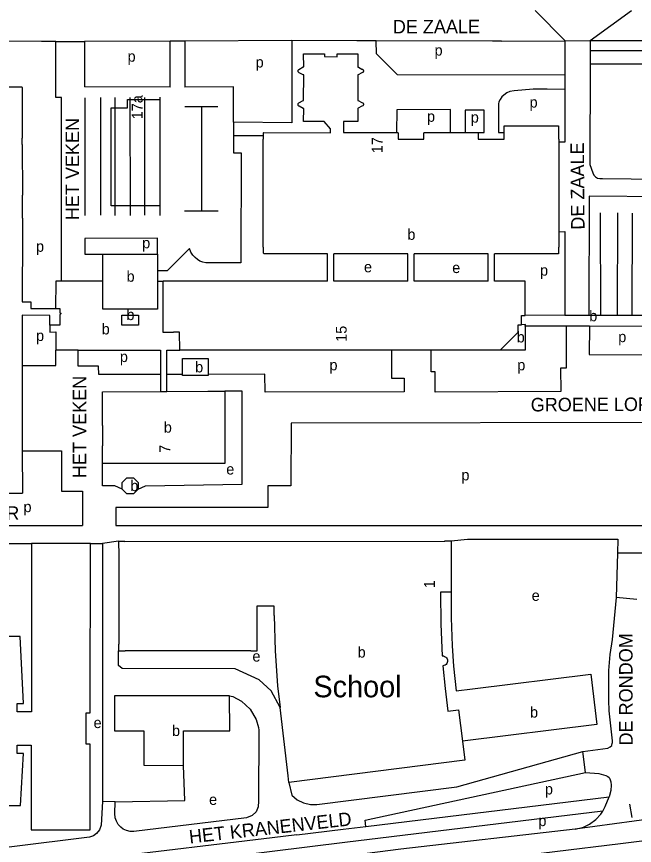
# Model space of a CAD drawing. Extents: x 161494 to 163033, y 383688 to 384862.
# Drawn here: x 162005.1 to 162234.2, y 384072.6 to 384379.7 of the extents above; entities that cross this region are included whole.
import ezdxf

# ---------------------------------------------------------------- set-up
doc = ezdxf.new("R2010")
doc.units = 0
for name, color, linetype in [('BLT_Basislijn', 7, 'Continuous'), ('BLT_Bebouwing', 7, 'Continuous'), ('BLT_Bebouwing_beschrifting', 7, 'Continuous'), ('BLT_Centroide', 7, 'Continuous'), ('BLT_Huisnummer', 7, 'Continuous'), ('BLT_Huisnummer_zonder_bebouwing', 7, 'Continuous'), ('BLT_Onderdoorgang_en_onderverdeling', 7, 'Continuous'), ('BLT_Onderverdeling_panden', 7, 'Continuous'), ('BLT_Plantopo', 7, 'Continuous'), ('BLT_Straatnaam', 7, 'Continuous'), ('BLT_Vlakafsluiter', 7, 'Continuous')]:
    doc.layers.add(name, color=color, linetype=linetype)

msp = doc.modelspace()

# ---------------------------------------------------------------- linework, layer by layer
at = {"layer": 'BLT_Basislijn'}
for p, q in [((162019.69, 384370.44), (162014.35, 384370.42)), ((162019.69, 384370.44), (162030.32, 384370.48)), ((162030.32, 384370.48), (162030.31, 384353.66)), ((162062.08, 384370.61), (162030.32, 384370.48)), ((162062.07, 384353.6), (162062.08, 384370.61)), ((162067.51, 384370.63), (162062.08, 384370.61)), ((162107.23, 384370.78), (162067.51, 384370.63)), ((162067.51, 384370.63), (162067.58, 384353.53)), ((162138.48, 384370.7), (162131.74, 384370.71)), ((162184.93, 384370.63), (162208.56, 384370.74)), ((162208.56, 384370.74), (162217.82, 384370.78)), ((162217.82, 384370.78), (162249.53, 384370.93)), ((162249.53, 384367.05), (162217.81, 384367.06)), ((162249.53, 384362.05), (162217.8, 384362.06)), ((162062.07, 384353.6), (162030.31, 384353.66)), ((162030.4, 384349.64), (162030.4, 384306.02)), ((162036.21, 384349.74), (162036.21, 384306.05)), ((162041.71, 384305.96), (162041.67, 384349.71)), ((162047.2, 384349.73), (162047.22, 384306)), ((162052.72, 384306.09), (162052.71, 384349.76)), ((162058.35, 384305.96), (162058.38, 384349.81)), ((162067.53, 384346.36), (162079.8, 384346.36)), ((162073.66, 384346.36), (162073.68, 384307.72)), ((162085.59, 384340.57), (162085.6, 384335.57)), ((162085.6, 384335.57), (162096.65, 384335.59)), ((162067.4, 384307.75), (162079.85, 384307.68)), ((162221.59, 384306.94), (162221.63, 384268.94)), ((162227.91, 384306.92), (162227.79, 384268.92)), ((162233.39, 384306.88), (162233.27, 384268.9)), ((162044.3, 384204.56), (162041.59, 384205.78)), ((161965.96, 384191.05), (162029.59, 384191.05)), ((161990.93, 384184.45), (162010.71, 384184.45)), ((162247.24, 384180.87), (162227.98, 384180.87)), ((162232.42, 384087.78), (162233.3, 384082.95)), ((162222.59, 384085.25), (162126.86, 384073.58)), ((162099.94, 384075.38), (162038.28, 384067.96)), ((162109.12, 384076.49), (162099.94, 384075.38)), ((162126.86, 384073.58), (162015.41, 384059.99))]:
    msp.add_line(p, q, dxfattribs=at)
for points in [[(162014.35, 384370.42), (161952.43, 384370.98)], [(162021.76, 384281.63), (162021.76, 384349.7), (162019.67, 384349.7), (162019.69, 384370.44)], [(162107.23, 384370.78), (162107.16, 384340.38), (162085.59, 384340.57)], [(162131.74, 384370.71), (162131.34, 384370.71), (162107.23, 384370.78)], [(162184.93, 384370.63), (162181.64, 384370.54), (162138.48, 384370.7)], [(162208.55, 384357.94), (162146.36, 384358.05), (162138.57, 384365.87), (162138.48, 384370.7)], [(162208.55, 384357.94), (162208.56, 384370.74)], [(162217.82, 384370.78), (162217.81, 384367.06)], [(162217.81, 384367.06), (162217.8, 384362.06)], [(162217.8, 384362.06), (162217.74, 384324.93), (162218.77, 384321.83), (162219.2, 384320.92), (162219.82, 384320.28), (162220.55, 384319.86), (162221.38, 384319.65), (162222.38, 384319.64), (162243.64, 384319.46), (162245.34, 384318.42), (162249.4, 384318.43), (162249.42, 384323.47)], [(162208.55, 384352.69), (162208.55, 384357.94)], [(162085.59, 384340.57), (162085.56, 384353.63), (162067.58, 384353.53)], [(162208.55, 384352.69), (162201.85, 384352.82), (162196.72, 384352.85), (162189.59, 384352.24), (162188.09, 384351.94), (162186.9, 384351.42), (162185.79, 384350.61), (162185.11, 384349.93), (162184.45, 384348.98), (162184, 384348.08), (162183.86, 384347.39), (162183.81, 384345.03), (162183.82, 384336.72), (162185.97, 384336.71)], [(162206.27, 384333.28), (162208.53, 384333.29), (162208.55, 384352.69)], [(162166.08, 384336.76), (162166.06, 384345.25), (162146.1, 384345.19), (162146.08, 384336.77)], [(162176.15, 384336.75), (162178.48, 384336.74), (162178.47, 384345.02), (162171.44, 384345.02), (162171.43, 384336.76)], [(162085.6, 384335.57), (162085.59, 384329.24), (162088.41, 384329.24), (162088.36, 384288.41), (162076.5, 384288.41), (162075.36, 384288.47), (162074.18, 384288.72), (162073.14, 384289.12), (162072.27, 384289.62), (162071.31, 384290.37), (162070.48, 384291.29), (162069.77, 384292.41), (162069.26, 384293.73), (162061.02, 384285.49), (162057.45, 384285.5)], [(162245.59, 384286.75), (162245.56, 384312.93), (162217.49, 384313.17), (162217.33, 384268.95)], [(162206.25, 384299.94), (162208.48, 384300.02), (162208.38, 384268.98)], [(162057.39, 384291.62), (162057.39, 384297.64), (162030.4, 384297.42), (162030.4, 384291.63), (162037.08, 384291.63)], [(162208.96, 384264.97), (162208.91, 384249.42), (162206.88, 384249.43), (162206.92, 384240.72), (162160.39, 384240.54), (162160.4, 384248.07), (162158.82, 384248.07), (162158.84, 384256.09)], [(162217.54, 384264.95), (162217.51, 384254.43), (162240.28, 384254.3), (162240.29, 384264.88)], [(162007.27, 384250.4), (162019.71, 384250.4), (162019.71, 384256.08)], [(162058.48, 384247.11), (162035.63, 384247.1), (162035.57, 384250.09), (162027.96, 384250.11), (162027.94, 384256.08)], [(162144.12, 384256.1), (162144.12, 384245.68), (162148.9, 384245.69), (162148.88, 384240.66), (162097.29, 384240.52), (162097.24, 384247.13), (162076.15, 384247.12)], [(162066.61, 384247.11), (162060.85, 384247.11)], [(162050.27, 384204.53), (162052.97, 384205.77), (162088.77, 384206.48), (162088.81, 384240.89), (162082.42, 384240.9)], [(162247.21, 384191.05), (162247.31, 384229.25), (162106.92, 384229), (162106.81, 384205.82), (162098.37, 384205.81), (162098.37, 384197.75), (162041.94, 384197.72), (162041.92, 384191.05), (162247.21, 384191.05)], [(162007.28, 384218.83), (162021.75, 384218.83), (162021.75, 384203.81), (162029.62, 384203.8), (162029.59, 384191.05)], [(162041.59, 384205.78), (162037, 384205.76), (162036.97, 384214.11)], [(162166.31, 384185.38), (162172.4, 384186.05), (162228.13, 384186.05)], [(162228.13, 384186.05), (162227.98, 384180.87)], [(162032.55, 384184.43), (162037.02, 384184.43)], [(162037.02, 384184.43), (162037.04, 384088.82)], [(162227.98, 384180.87), (162227.52, 384164.46)], [(162227.52, 384164.46), (162226.02, 384148.8)], [(162226.02, 384148.8), (162225.15, 384143.31), (162224.67, 384137.43), (162224.57, 384126.39), (162224.74, 384122.4), (162225.26, 384117.92)], [(162102.89, 384123.64), (162099.51, 384129.85), (162095.13, 384133.9), (162086.14, 384137.97), (162044.34, 384138.09), (162042.99, 384139.27), (162042.97, 384144.67)], [(162084.15, 384127.98), (162085.35, 384127.68), (162088.53, 384126.04), (162091.72, 384123), (162093.98, 384119.23), (162094.84, 384116.31), (162094.96, 384115.27), (162094.86, 384088.92), (162094.74, 384086.81), (162093.96, 384085.04), (162092.56, 384083.64), (162090.45, 384082.79), (162048.68, 384077.67), (162047.3, 384077.68), (162045.86, 384078.03), (162044.73, 384078.57), (162043.77, 384079.28), (162042.84, 384080.31), (162042.15, 384081.53), (162041.75, 384082.79), (162041.62, 384084.43), (162041.68, 384088.69)], [(162225.26, 384117.92), (162226.02, 384111.31), (162226.02, 384110.45)], [(162215.09, 384107.35), (162224.34, 384108.57), (162225.26, 384109.03), (162225.82, 384109.61), (162226.02, 384110.45)], [(162106.09, 384095.92), (162107.27, 384091.16), (162109.14, 384089.5), (162111.49, 384088.28), (162114.17, 384087.69), (162116.52, 384087.75), (162168.4, 384094.24), (162215.09, 384107.35)], [(162041.68, 384088.69), (162067.5, 384089.14), (162067.07, 384102.21)], [(162134.69, 384079.58), (162134.41, 384081.91), (162216.12, 384099.58)], [(162216.12, 384099.58), (162221.09, 384099.24), (162223.58, 384098.49), (162224.36, 384098.12), (162224.84, 384097.7), (162225.1, 384097.23), (162225.48, 384096.06), (162225.64, 384094.84), (162225.46, 384092.91), (162224.84, 384090.56)], [(162134.69, 384079.58), (162224.84, 384090.56)], [(162222.59, 384085.25), (162223.45, 384086.96), (162224.84, 384090.56)], [(162037.04, 384088.82), (162036.53, 384080.07), (162035.9, 384078.31), (162034.83, 384076.99), (162033.62, 384076.14), (162032.14, 384075.62), (161973.45, 384068.36), (161971.82, 384068.3), (161970.32, 384068.57), (161968.94, 384069.14), (161967.71, 384069.97), (161966.53, 384071.23), (161965.71, 384072.68), (161965.29, 384073.99), (161965.13, 384075.37), (161965.09, 384077.77), (161965.12, 384080.52)], [(162041.68, 384088.69), (162037.04, 384088.82)], [(162212.3, 384078.63), (162215.37, 384079.36), (162217.58, 384080.42), (162219.99, 384082.13), (162221.75, 384084.12), (162222.59, 384085.25)], [(162212.3, 384078.63), (162147.57, 384071.14), (162099.53, 384065.02), (162042.92, 384058.28)], [(162109.12, 384076.49), (162126.25, 384078.55), (162134.69, 384079.58)], [(162257.94, 384076.77), (162229.07, 384073.11), (162180.34, 384067.19), (162170.91, 384066.06)]]:
    msp.add_lwpolyline(points, dxfattribs=at)
at = {"layer": 'BLT_Bebouwing'}
for p, q in [((162007.37, 384304.96), (162007.37, 384313.57)), ((162120.44, 384281.64), (162120.44, 384291.78)), ((162122.84, 384281.64), (162122.81, 384291.78)), ((162150.21, 384281.65), (162150.18, 384291.78)), ((162152.58, 384281.65), (162152.58, 384291.78)), ((162179.98, 384281.65), (162179.97, 384291.78)), ((162182.33, 384281.65), (162182.36, 384291.78)), ((162057.45, 384281.64), (162059.53, 384281.65)), ((162208.38, 384268.98), (162193.79, 384269.02)), ((162217.33, 384268.95), (162208.38, 384268.98)), ((162221.63, 384268.94), (162217.33, 384268.95)), ((162227.79, 384268.92), (162221.63, 384268.94)), ((162233.27, 384268.9), (162227.79, 384268.92)), ((162238.76, 384268.88), (162233.27, 384268.9)), ((162208.96, 384264.97), (162193.79, 384265.02)), ((162217.54, 384264.95), (162208.96, 384264.97)), ((162240.29, 384264.88), (162217.54, 384264.95)), ((162027.94, 384256.08), (162019.71, 384256.08)), ((162076.15, 384252.99), (162076.15, 384247.12)), ((162076.15, 384247.12), (162076.15, 384246.67)), ((162007.27, 384234.35), (162007.28, 384218.83)), ((162166.31, 384185.38), (162166.3, 384166.4)), ((162084.15, 384127.98), (162041.43, 384127.99)), ((162105.91, 384098.32), (162102.89, 384123.64)), ((162220.29, 384117.37), (162170.48, 384111.23))]:
    msp.add_line(p, q, dxfattribs=at)
for points in [[(162111.61, 384361.02), (162111.59, 384365.87), (162119.27, 384365.88), (162119.28, 384364.88), (162124, 384364.84), (162124, 384365.86), (162131.7, 384365.86), (162131.68, 384361)], [(162111.6, 384358.05), (162111.43, 384358.05), (162109.98, 384358.89), (162109.82, 384358.97), (162109.71, 384359.07), (162109.63, 384359.18), (162109.58, 384359.28), (162109.55, 384359.36), (162109.53, 384359.46), (162109.52, 384359.58), (162109.55, 384359.76), (162109.61, 384359.88), (162109.67, 384359.98), (162109.82, 384360.12), (162111.41, 384361.02), (162111.61, 384361.02)], [(162131.68, 384361), (162131.87, 384361), (162133.19, 384360.27), (162133.43, 384360.16), (162133.53, 384360.09), (162133.62, 384359.98), (162133.71, 384359.83), (162133.75, 384359.68), (162133.76, 384359.55), (162133.76, 384359.46), (162133.75, 384359.36), (162133.7, 384359.23), (162133.63, 384359.1), (162133.56, 384359.02), (162133.45, 384358.93), (162133.21, 384358.82), (162131.86, 384358.08), (162131.67, 384358.08)], [(162111.59, 384348.6), (162111.6, 384358.05)], [(162131.67, 384358.08), (162131.68, 384348.64)], [(161975.98, 384353.62), (162000, 384353.62), (162007.04, 384353.64), (162007.04, 384353.41), (162007.27, 384353.41), (162007.26, 384334.69)], [(162111.6, 384345.67), (162111.42, 384345.67), (162109.92, 384346.5), (162109.81, 384346.55), (162109.72, 384346.62), (162109.64, 384346.71), (162109.58, 384346.8), (162109.52, 384346.95), (162109.5, 384347.09), (162109.5, 384347.23), (162109.54, 384347.37), (162109.6, 384347.48), (162109.66, 384347.57), (162109.74, 384347.65), (162109.85, 384347.72), (162111.39, 384348.6), (162111.59, 384348.6)], [(162131.68, 384348.64), (162131.84, 384348.65), (162133.22, 384347.9), (162133.52, 384347.73), (162133.59, 384347.66), (162133.67, 384347.56), (162133.72, 384347.46), (162133.76, 384347.32), (162133.77, 384347.17), (162133.76, 384347.07), (162133.74, 384346.94), (162133.69, 384346.83), (162133.63, 384346.73), (162133.56, 384346.66), (162133.49, 384346.59), (162133.21, 384346.46), (162131.85, 384345.7), (162131.69, 384345.69)], [(162096.65, 384335.59), (162096.65, 384336.56), (162096.86, 384336.77), (162121.5, 384336.6), (162121.53, 384338.14), (162119.21, 384340.78), (162111.58, 384340.81), (162111.6, 384345.67)], [(162131.69, 384345.69), (162131.68, 384340.82), (162126.38, 384340.82), (162126.38, 384336.77), (162146.08, 384336.77)], [(162185.97, 384336.71), (162185.99, 384339.2), (162206.11, 384339.2)], [(162206.11, 384339.2), (162206.09, 384334.29), (162206.27, 384334.29), (162206.27, 384333.28)], [(162120.44, 384291.78), (162096.87, 384291.78), (162096.66, 384291.99), (162096.65, 384294.23), (162096.54, 384294.24), (162096.52, 384334.32), (162096.65, 384334.32), (162096.65, 384335.59)], [(162146.08, 384336.77), (162146.38, 384336.77), (162146.59, 384336.56), (162146.58, 384334.3)], [(162146.58, 384334.3), (162156.19, 384334.32), (162156.19, 384336.56), (162156.39, 384336.77), (162166.08, 384336.76)], [(162166.08, 384336.76), (162171.43, 384336.76)], [(162171.43, 384336.76), (162176.15, 384336.75)], [(162176.15, 384336.75), (162176.36, 384336.55), (162176.36, 384334.24), (162185.95, 384334.24), (162185.97, 384336.71)], [(162007.26, 384332.31), (162007.37, 384313.57)], [(162206.27, 384333.28), (162206.25, 384299.94)], [(162007.37, 384304.96), (162007.36, 384300), (162007.28, 384274)], [(162206.25, 384299.94), (162206.25, 384294.23), (162206.07, 384294.23), (162206.08, 384291.78)], [(162037.08, 384281.64), (162037.08, 384291.63)], [(162037.08, 384291.63), (162057.39, 384291.62)], [(162057.39, 384291.62), (162057.45, 384291.62), (162057.45, 384285.5)], [(162150.18, 384291.78), (162122.81, 384291.78)], [(162179.97, 384291.78), (162152.58, 384291.78)], [(162206.08, 384291.78), (162182.36, 384291.78)], [(162057.45, 384285.5), (162057.45, 384281.64)], [(162021.76, 384281.63), (162019.7, 384281.63), (162019.63, 384271.53)], [(162023.61, 384281.64), (162021.76, 384281.63)], [(162033.74, 384281.64), (162023.61, 384281.64)], [(162037.08, 384281.64), (162033.74, 384281.64)], [(162057.45, 384281.64), (162057.46, 384271.23)], [(162120.44, 384281.64), (162059.53, 384281.65)], [(162150.21, 384281.65), (162122.84, 384281.64)], [(162179.98, 384281.65), (162152.58, 384281.65)], [(162193.79, 384269.02), (162193.79, 384281.63), (162182.33, 384281.65)], [(162007.28, 384274), (162010.42, 384273.99), (162010.43, 384271.54), (162019.63, 384271.53)], [(162017.45, 384265.29), (162017.44, 384268.98), (162007.27, 384269.03), (162007.27, 384250.4)], [(162017.45, 384265.29), (162017.5, 384262.78), (162019.7, 384262.82), (162019.71, 384256.08)], [(162193.79, 384265.02), (162193.72, 384256.08), (162184.4, 384256.08)], [(162027.94, 384256.08), (162033.74, 384256.08)], [(162033.74, 384256.08), (162058.46, 384256.07), (162058.48, 384247.11)], [(162060.85, 384247.11), (162060.82, 384256.11), (162065.64, 384256.13)], [(162144.12, 384256.1), (162065.64, 384256.13)], [(162158.84, 384256.09), (162144.12, 384256.1)], [(162184.4, 384256.08), (162158.84, 384256.09)], [(162066.61, 384247.11), (162066.61, 384253), (162076.15, 384252.99)], [(162007.27, 384250.4), (162007.27, 384234.35)], [(162058.48, 384247.11), (162058.49, 384240.8)], [(162060.87, 384240.81), (162060.85, 384247.11)], [(162076.15, 384246.67), (162066.61, 384246.69), (162066.61, 384247.11)], [(162082.42, 384240.9), (162082.42, 384236.98), (162082.39, 384214.11), (162036.97, 384214.11)], [(162037, 384240.67), (162058.49, 384240.8)], [(162037, 384234.35), (162037, 384240.67)], [(162060.87, 384240.81), (162076.03, 384240.9), (162082.42, 384240.9)], [(162036.97, 384214.11), (162036.98, 384220.59), (162037.08, 384220.59), (162037.1, 384228.13), (162037, 384228.13), (162037, 384234.35)], [(162007.28, 384218.83), (162007.29, 384203.04)], [(162044.3, 384204.56), (162044.28, 384207.05), (162046.04, 384208.79), (162048.52, 384208.8), (162050.26, 384207.02), (162050.27, 384204.53)], [(161965.95, 384203.08), (162000, 384203.09), (162007.29, 384203.04)], [(162050.27, 384204.53), (162048.51, 384202.8), (162046.04, 384202.79), (162044.3, 384204.56)], [(162042.92, 384185.26), (162045.33, 384185.26), (162045.33, 384185.13), (162163.9, 384185.26), (162163.9, 384185.37), (162166.31, 384185.38)], [(162042.92, 384185.26), (162042.95, 384182.84), (162043.06, 384182.56), (162043.1, 384147.07), (162042.99, 384147.07), (162042.97, 384144.67)], [(162010.71, 384184.45), (162010.64, 384122.06), (162005.38, 384122.07), (162005.38, 384125.2), (162007.7, 384125.2), (162006.42, 384149.99), (161995.16, 384149.99), (161993.82, 384125.21), (161996.14, 384125.21), (161996.14, 384122.06), (161990.88, 384122.07), (161990.93, 384184.45)], [(162032.55, 384184.43), (162010.71, 384184.45)], [(162032.45, 384078.34), (162032.48, 384110.05), (162030.94, 384110.05), (162030.95, 384121.73), (162032.46, 384121.73), (162032.55, 384184.43)], [(162166.3, 384166.4), (162166.29, 384156.92), (162166.66, 384146.5), (162167.18, 384138.92), (162168.12, 384129.86), (162174.23, 384130.62)], [(162042.97, 384144.67), (162045.37, 384144.68), (162045.37, 384144.79), (162091.98, 384144.83), (162091.98, 384144.72), (162094.37, 384144.71), (162094.35, 384161.39)], [(162094.35, 384161.39), (162100.55, 384161.38), (162100.58, 384157.72), (162100.68, 384157.72), (162101.03, 384144.71), (162101.89, 384131.73), (162102.89, 384123.64)], [(162174.23, 384130.62), (162218.04, 384136.07)], [(162218.04, 384136.07), (162220.29, 384117.37)], [(162041.43, 384127.99), (162041.43, 384115.01), (162052.32, 384115), (162052.34, 384102.23), (162067.07, 384102.21)], [(162067.07, 384102.21), (162067.08, 384115), (162084.16, 384115), (162084.15, 384127.98)], [(161970.56, 384117.96), (161970.55, 384110.1), (161969.01, 384110.1), (161968.99, 384078.41), (161990.85, 384078.38), (161990.87, 384109.77), (161996.16, 384109.78), (161996.13, 384106.62), (161993.8, 384106.62), (161994.79, 384087.31), (162006.64, 384087.31), (162007.69, 384106.6), (162005.36, 384106.61), (162005.37, 384109.74), (162010.59, 384109.74), (162010.6, 384078.36), (162032.45, 384078.34)], [(162170.48, 384111.23), (162171.36, 384104.09), (162106.09, 384095.92)], [(162106.09, 384095.92), (162105.8, 384098.3), (162105.91, 384098.32)]]:
    msp.add_lwpolyline(points, dxfattribs=at)
at = {"layer": 'BLT_Onderdoorgang_en_onderverdeling'}
msp.add_line((162058.49, 384240.8), (162060.87, 384240.81), dxfattribs=at)
for points in [[(162057.46, 384271.23), (162037.08, 384271.25), (162037.08, 384281.64)], [(162065.64, 384256.13), (162065.61, 384262.8), (162063.28, 384262.78), (162063.28, 384262.68), (162059.48, 384262.67), (162059.53, 384281.65)], [(162021.22, 384271.53), (162021.23, 384269.97), (162021.28, 384269.97), (162021.33, 384269.94), (162021.38, 384269.92), (162021.42, 384269.89), (162021.46, 384269.84), (162021.49, 384269.79), (162021.52, 384269.73), (162021.52, 384269.66), (162021.51, 384269.57), (162021.48, 384269.49), (162021.43, 384269.43), (162021.36, 384269.38), (162021.3, 384269.35), (162021.23, 384269.34), (162021.22, 384265.29), (162017.45, 384265.29)], [(162019.63, 384271.53), (162021.22, 384271.53)], [(162050.31, 384265.34), (162044.14, 384265.34), (162044.14, 384269.07), (162050.31, 384269.07), (162050.31, 384265.34)], [(162192.34, 384265.51), (162192.34, 384268.97), (162193.79, 384268.97), (162193.79, 384269.02)], [(162184.4, 384256.08), (162191.12, 384262.79), (162191.11, 384265.5), (162192.34, 384265.51)], [(162193.79, 384265.02), (162193.8, 384265.54), (162192.34, 384265.51)], [(162166.3, 384166.4), (162162.38, 384166.41), (162162.42, 384154.58), (162162.93, 384142.76), (162163.39, 384142.75), (162163.88, 384142.6), (162164.3, 384142.35), (162164.6, 384142.02), (162164.79, 384141.72), (162164.9, 384141.38), (162164.94, 384141.08), (162164.95, 384140.71), (162164.84, 384140.32), (162164.66, 384139.93), (162164.39, 384139.62), (162164.07, 384139.35), (162163.62, 384139.19), (162163.21, 384139.11), (162164.08, 384130.73), (162165.11, 384122.36), (162169.05, 384122.85), (162170.48, 384111.23)]]:
    msp.add_lwpolyline(points, dxfattribs=at)
at = {"layer": 'BLT_Onderverdeling_panden'}
msp.add_line((162007.26, 384332.31), (162007.26, 384334.69), dxfattribs=at)
at = {"layer": 'BLT_Plantopo'}
msp.add_lwpolyline([(162040.18, 384345.82), (162046.24, 384345.82), (162046.24, 384348.98), (162058.3, 384348.98), (162058.3, 384309.59), (162040.18, 384309.59)], close=True, dxfattribs=at)
at = {"layer": 'BLT_Vlakafsluiter'}
for p, q in [((162197.47, 384381.94), (162208.56, 384370.74)), ((162217.82, 384370.78), (162233.21, 384381.92)), ((162042.92, 384185.26), (162037.02, 384184.43)), ((162235.09, 384163.69), (162227.52, 384164.46)), ((162216.12, 384099.58), (162215.09, 384107.35)), ((162246.45, 384083.27), (162212.3, 384078.63))]:
    msp.add_line(p, q, dxfattribs=at)

# ---------------------------------------------------------------- texts
at = {"layer": 'BLT_Bebouwing_beschrifting'}
msp.add_text('School', height=8, dxfattribs=at).set_placement((162115.2, 384127.44))
at = {"layer": 'BLT_Centroide'}
for s, p in [('p', (162046.3, 384362.97)), ('p', (162160.13, 384365.23)), ('p', (162093.79, 384360.83)), ('p', (162195.37, 384345.97)), ('p', (162157.34, 384340.72)), ('p', (162173.57, 384340.41)), ('b', (162150.06, 384296.97)), ('p', (162012.36, 384292.55)), ('p', (162051.72, 384293.83)), ('e', (162133.97, 384284.94)), ('e', (162166.68, 384284.65)), ('p', (162199.25, 384283.7)), ('b', (162045.93, 384281.44)), ('b', (162045.89, 384267.22)), ('b', (162217.49, 384266.8)), ('b', (162036.72, 384261.92)), ('p', (162012.38, 384259.47)), ('b', (162190.6, 384258.94)), ('p', (162228.24, 384259.05)), ('p', (162043.45, 384251.68)), ('b', (162071.37, 384247.84)), ('p', (162121.17, 384248.6)), ('p', (162190.8, 384248.6)), ('b', (162059.75, 384225.5)), ('e', (162082.89, 384210)), ('p', (162170.1, 384207.82)), ('b', (162047.35, 384203.84)), ('p', (162007.72, 384196.05)), ('e', (162196.16, 384163.18)), ('b', (162131.61, 384142.17)), ('e', (162092.61, 384140.68)), ('b', (162195.54, 384119.94)), ('e', (162033.7, 384116.03)), ('b', (162062.79, 384113.09)), ('p', (162201.06, 384091.45)), ('e', (162076.53, 384087.56)), ('p', (162198.65, 384079.71))]:
    msp.add_text(s, height=4, dxfattribs=at).set_placement(p)
at = {"layer": 'BLT_Huisnummer'}
for s, rotation, p in [('17', 90.1214, (162140.85, 384329.06)), ('15', 90.1214, (162127.55, 384259.17)), ('7', 90.1214, (162062.14, 384218.04)), ('1', 90.0482, (162160.26, 384167.88))]:
    msp.add_text(s, height=4, rotation=rotation, dxfattribs=at).set_placement(p)
at = {"layer": 'BLT_Huisnummer_zonder_bebouwing'}
msp.add_text('17a', height=4, rotation=90.1214, dxfattribs=at).set_placement((162051.88, 384341.65))
at = {"layer": 'BLT_Straatnaam'}
for s, rotation, p in [('DE ZAALE', 0.1418, (162144.66, 384373.45)), ('HET VEKEN', 89.9778, (162028.31, 384304.24)), ('DE ZAALE', 90.47, (162215.77, 384300.75)), ('HET VEKEN', 89.9778, (162030.99, 384208.68)), ('GROENE LOPER', 0.2472, (162195.8, 384233.37)), ('GROENE LOPER', 0.2472, (161952.67, 384192.99)), ('DE RONDOM', 90.0852, (162233.59, 384109.59)), ('HET KRANENVELD', 6.4105, (162069.38, 384073.25))]:
    msp.add_text(s, height=5, rotation=rotation, dxfattribs=at).set_placement(p)

doc.saveas('drawing.dxf')
